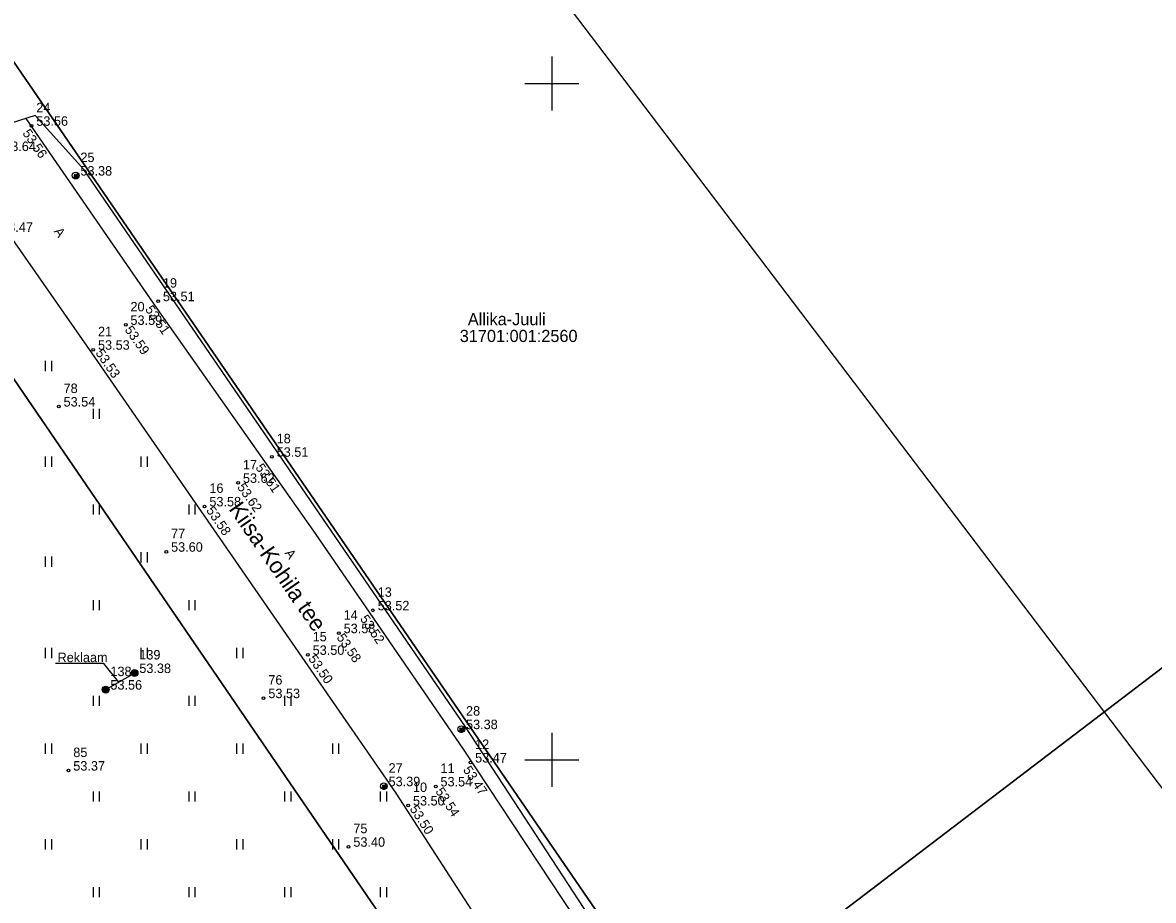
# Model space of a CAD drawing. Extents: x 538599 to 541973, y 6559689 to 6564516.
# Drawn here: x 540610.9 to 540694.4, y 6561289.6 to 6561354.5 of the extents above; entities that cross this region are included whole.
import ezdxf

# ---------------------------------------------------------------- set-up
doc = ezdxf.new("R2010")
doc.units = 0
for name, color, linetype in [('HALJASTUS', 7, 'Continuous'), ('KORGUS-EH2000', 7, 'Continuous'), ('MOOTKORG-EH2000', 7, 'Continuous'), ('MOOTMPUNKT', 7, 'Continuous'), ('MOOTNR', 7, 'Continuous'), ('MOOTPIIR', 7, 'Continuous'), ('PIIR', 7, 'Continuous'), ('POST', 7, 'Continuous'), ('RAJATIS', 7, 'Continuous'), ('TEE', 7, 'Continuous'), ('VORK', 7, 'Continuous'), ('VORMISTUS', 7, 'Continuous')]:
    doc.layers.add(name, color=color, linetype=linetype)

msp = doc.modelspace()

# ---------------------------------------------------------------- linework, layer by layer
at = {"layer": 'HALJASTUS'}
for p, q in [((540612.567, 6561329.498), (540612.567, 6561328.737)), ((540613.022, 6561329.498), (540613.022, 6561328.737)), ((540616.103, 6561325.962), (540616.103, 6561325.201)), ((540616.558, 6561325.962), (540616.558, 6561325.201)), ((540612.567, 6561322.427), (540612.567, 6561321.666)), ((540613.022, 6561322.427), (540613.022, 6561321.666)), ((540619.638, 6561322.427), (540619.638, 6561321.666)), ((540620.093, 6561322.427), (540620.093, 6561321.666)), ((540616.103, 6561318.891), (540616.103, 6561318.13)), ((540616.558, 6561318.891), (540616.558, 6561318.13)), ((540623.174, 6561318.891), (540623.174, 6561318.13)), ((540623.629, 6561318.891), (540623.629, 6561318.13)), ((540612.567, 6561315.033), (540612.567, 6561314.271)), ((540613.022, 6561315.033), (540613.022, 6561314.271)), ((540619.638, 6561315.356), (540619.638, 6561314.595)), ((540620.093, 6561315.356), (540620.093, 6561314.595)), ((540616.103, 6561311.82), (540616.103, 6561311.059)), ((540616.558, 6561311.82), (540616.558, 6561311.059)), ((540623.174, 6561311.82), (540623.174, 6561311.059)), ((540623.629, 6561311.82), (540623.629, 6561311.059)), ((540612.567, 6561308.285), (540612.567, 6561307.524)), ((540613.022, 6561308.285), (540613.022, 6561307.524)), ((540619.638, 6561308.285), (540619.638, 6561307.524)), ((540620.093, 6561308.285), (540620.093, 6561307.524)), ((540626.709, 6561308.285), (540626.709, 6561307.524)), ((540627.164, 6561308.285), (540627.164, 6561307.524)), ((540616.103, 6561304.749), (540616.103, 6561303.988)), ((540616.558, 6561304.749), (540616.558, 6561303.988)), ((540623.174, 6561304.749), (540623.174, 6561303.988)), ((540623.629, 6561304.749), (540623.629, 6561303.988)), ((540630.245, 6561304.749), (540630.245, 6561303.988)), ((540630.7, 6561304.749), (540630.7, 6561303.988)), ((540612.567, 6561301.214), (540612.567, 6561300.453)), ((540613.022, 6561301.214), (540613.022, 6561300.453)), ((540619.638, 6561301.214), (540619.638, 6561300.453)), ((540620.093, 6561301.214), (540620.093, 6561300.453)), ((540626.709, 6561301.214), (540626.709, 6561300.453)), ((540627.164, 6561301.214), (540627.164, 6561300.453)), ((540633.78, 6561301.214), (540633.78, 6561300.453)), ((540634.235, 6561301.214), (540634.235, 6561300.453)), ((540616.103, 6561297.678), (540616.103, 6561296.917)), ((540616.558, 6561297.678), (540616.558, 6561296.917)), ((540623.174, 6561297.678), (540623.174, 6561296.917)), ((540623.629, 6561297.678), (540623.629, 6561296.917)), ((540630.245, 6561297.678), (540630.245, 6561296.917)), ((540630.7, 6561297.678), (540630.7, 6561296.917)), ((540637.316, 6561297.678), (540637.316, 6561296.917)), ((540637.771, 6561297.678), (540637.771, 6561296.917)), ((540612.567, 6561294.143), (540612.567, 6561293.381)), ((540613.022, 6561294.143), (540613.022, 6561293.381)), ((540619.638, 6561294.143), (540619.638, 6561293.381)), ((540620.093, 6561294.143), (540620.093, 6561293.381)), ((540626.709, 6561294.143), (540626.709, 6561293.381)), ((540627.164, 6561294.143), (540627.164, 6561293.381)), ((540633.78, 6561294.143), (540633.78, 6561293.381)), ((540634.235, 6561294.143), (540634.235, 6561293.381)), ((540616.103, 6561290.607), (540616.103, 6561289.846)), ((540616.558, 6561290.607), (540616.558, 6561289.846)), ((540623.174, 6561290.607), (540623.174, 6561289.846)), ((540623.629, 6561290.607), (540623.629, 6561289.846)), ((540630.245, 6561290.607), (540630.245, 6561289.846)), ((540630.7, 6561290.607), (540630.7, 6561289.846)), ((540637.316, 6561290.607), (540637.316, 6561289.846)), ((540637.771, 6561290.607), (540637.771, 6561289.846))]:
    msp.add_line(p, q, dxfattribs=at)
at = {"layer": 'KORGUS-EH2000'}
for centre in [(540611.557, 6561346.872), (540620.91, 6561333.908), (540618.513, 6561332.154), (540616.114, 6561330.319), (540613.571, 6561326.12), (540629.315, 6561322.407), (540626.823, 6561320.477), (540624.343, 6561318.738), (540621.513, 6561315.389), (540636.779, 6561311.056), (540634.264, 6561309.368), (540631.973, 6561307.767), (540628.7, 6561304.567), (540643.977, 6561299.809), (540614.288, 6561299.21), (540641.418, 6561298.042), (540639.384, 6561296.631), (540634.98, 6561293.583)]:
    msp.add_circle(centre, 0.1, dxfattribs=at)
at = {"layer": 'MOOTMPUNKT'}
for centre in [(540611.557, 6561346.872), (540614.816, 6561343.191), (540620.91, 6561333.908), (540618.513, 6561332.154), (540616.114, 6561330.319), (540613.571, 6561326.12), (540629.315, 6561322.407), (540626.823, 6561320.477), (540624.343, 6561318.738), (540621.513, 6561315.389), (540636.779, 6561311.056), (540634.264, 6561309.368), (540631.973, 6561307.767), (540619.167, 6561306.424), (540617.031, 6561305.196), (540628.7, 6561304.567), (540643.306, 6561302.276), (540643.977, 6561299.809), (540614.288, 6561299.21), (540637.582, 6561298.057), (540641.418, 6561298.042), (540639.384, 6561296.631), (540634.98, 6561293.583)]:
    msp.add_circle(centre, 0.1, dxfattribs=at)
at = {"layer": 'MOOTPIIR'}
msp.add_lwpolyline([(540582.869, 6561222.817), (540621.742, 6561247.747), (540640.195, 6561259.582), (540660.245, 6561276.551), (540652.795, 6561288.389), (540643.616, 6561302.458), (540615.416, 6561343.631), (540611.814, 6561347.628), (540600.551, 6561344.045)], dxfattribs=at)
at = {"layer": 'PIIR'}
for points in [[(540290.72, 6561746.68), (540427.24, 6561588.74), (540493.94, 6561511.13), (540543.58, 6561450.93), (540540.24, 6561448.03), (540578.89, 6561396.62), (540600.99, 6561365.08), (540659.54, 6561279.7), (540697.59, 6561212.89), (540728.6, 6561157.63), (540756.94, 6561107.21), (540762.6, 6561098.5), (540765.3, 6561101.59), (540815.83, 6561019.53), (540863.6, 6560935.22), (540880.61, 6560910.09), (540903.4, 6560875.14), (540927.11, 6560842.51), (540955.71, 6560805.99), (540982.2, 6560772.63), (541049.12, 6560693.03)], [(541045.65, 6560666.8), (540964.7, 6560765.19), (540868.94, 6560895.75), (540756.19, 6561084.56), (540744.95, 6561099.98), (540716.4, 6561150.76), (540687.02, 6561204.55), (540646.74, 6561272.89), (540640.63, 6561283.66), (540606.26, 6561333.96), (540569.6, 6561385.93), (540537.11, 6561431.06), (540500.82, 6561475.34), (540460.86, 6561522.64), (540423.13, 6561566.69), (540380.29, 6561616.49), (540342.1, 6561660.8)]]:
    msp.add_lwpolyline(points, dxfattribs=at)
for points in [[(540600.99, 6561365.08), (540701.8, 6561446.25), (540826.84, 6561548.44), (540828.67, 6561550.37), (540829.75, 6561549.48), (540833.57, 6561546.34), (540844.1, 6561537.92), (540853.65, 6561531.83), (540859.93, 6561522.78), (540863.38, 6561506.22), (540873.29, 6561464.28), (540881.92, 6561432.26), (540885.77, 6561408.65), (540892.47, 6561398.48), (540907.42, 6561381.68), (540938.49, 6561347.15), (540935.17, 6561343.58), (540808.31, 6561283.67), (540793.04, 6561301.15), (540771.58, 6561325.47), (540750.46, 6561349.5), (540705.14, 6561314.47), (540659.54, 6561279.7)], [(540535.92, 6561287.97), (540606.26, 6561333.96), (540640.63, 6561283.66), (540573.77, 6561238.75)], [(540659.54, 6561279.7), (540705.14, 6561314.47), (540727.47, 6561291.02), (540772.2, 6561324.85), (540793.34, 6561300.57), (540697.59, 6561212.89)]]:
    msp.add_lwpolyline(points, close=True, dxfattribs=at)
at = {"layer": 'POST'}
for p, q in [((540614.639, 6561343.015), (540614.993, 6561343.368)), ((540643.129, 6561302.1), (540643.483, 6561302.453)), ((540637.405, 6561297.881), (540637.759, 6561298.234))]:
    msp.add_line(p, q, dxfattribs=at)
for centre, radius in [((540614.816, 6561343.191), 0.25), ((540619.167, 6561306.424), 0.25), ((540619.167, 6561306.424), 0.225), ((540619.167, 6561306.424), 0.2), ((540619.167, 6561306.424), 0.175), ((540619.167, 6561306.424), 0.15), ((540619.167, 6561306.424), 0.125), ((540619.167, 6561306.424), 0.1), ((540619.167, 6561306.424), 0.075), ((540619.167, 6561306.424), 0.05), ((540619.167, 6561306.424), 0.025), ((540617.031, 6561305.196), 0.25), ((540617.031, 6561305.196), 0.225), ((540617.031, 6561305.196), 0.2), ((540617.031, 6561305.196), 0.175), ((540617.031, 6561305.196), 0.15), ((540617.031, 6561305.196), 0.125), ((540617.031, 6561305.196), 0.1), ((540617.031, 6561305.196), 0.075), ((540617.031, 6561305.196), 0.05), ((540617.031, 6561305.196), 0.025), ((540643.306, 6561302.276), 0.25), ((540637.582, 6561298.057), 0.25)]:
    msp.add_circle(centre, radius, dxfattribs=at)
for centre, radius, start, end in [((540614.816, 6561343.191), 0.225, 224.85406, 45.03563), ((540614.816, 6561343.191), 0.2, 224.84272, 45.04698), ((540614.816, 6561343.191), 0.175, 224.82813, 45.06157), ((540614.816, 6561343.191), 0.15, 224.80867, 45.08103), ((540614.816, 6561343.191), 0.125, 224.78144, 45.10826), ((540614.816, 6561343.191), 0.1, 224.74058, 45.14911), ((540614.816, 6561343.191), 0.075, 224.67249, 45.2172), ((540614.816, 6561343.191), 0.05, 224.53632, 45.35338), ((540614.816, 6561343.191), 0.025, 224.12776, 45.76193), ((540643.306, 6561302.276), 0.225, 224.85406, 45.03563), ((540643.306, 6561302.276), 0.2, 224.84272, 45.04698), ((540643.306, 6561302.276), 0.175, 224.82813, 45.06157), ((540643.306, 6561302.276), 0.15, 224.80867, 45.08103), ((540643.306, 6561302.276), 0.125, 224.78144, 45.10826), ((540643.306, 6561302.276), 0.1, 224.74058, 45.14911), ((540643.306, 6561302.276), 0.075, 224.67249, 45.2172), ((540643.306, 6561302.276), 0.05, 224.53632, 45.35338), ((540643.306, 6561302.276), 0.025, 224.12776, 45.76193), ((540637.582, 6561298.057), 0.225, 224.85406, 45.03563), ((540637.582, 6561298.057), 0.2, 224.84272, 45.04698), ((540637.582, 6561298.057), 0.175, 224.82813, 45.06157), ((540637.582, 6561298.057), 0.15, 224.80867, 45.08103), ((540637.582, 6561298.057), 0.125, 224.78144, 45.10826), ((540637.582, 6561298.057), 0.1, 224.74058, 45.14911), ((540637.582, 6561298.057), 0.075, 224.67249, 45.2172), ((540637.582, 6561298.057), 0.05, 224.53632, 45.35338), ((540637.582, 6561298.057), 0.025, 224.12776, 45.76193)]:
    msp.add_arc(centre, radius, start, end, dxfattribs=at)
at = {"layer": 'RAJATIS'}
for points in [[(540618.011, 6561305.759), (540616.903, 6561307.116), (540613.318, 6561307.116)], [(540617.031, 6561305.196), (540619.167, 6561306.424)]]:
    msp.add_lwpolyline(points, dxfattribs=at)
at = {"layer": 'TEE'}
for points in [[(540611.142, 6561347.415), (540620.815, 6561333.355), (540632.508, 6561316.728), (540643.438, 6561300.807), (540653.575, 6561285.476), (540659.181, 6561275.65)], [(540654.57, 6561271.748), (540648.314, 6561282.335), (540638.501, 6561297.54), (540627.363, 6561313.661), (540616.232, 6561329.779), (540605.221, 6561345.531)]]:
    msp.add_lwpolyline(points, dxfattribs=at)
at = {"layer": 'VORK'}
for p, q in [((540650, 6561352), (540650, 6561348)), ((540648, 6561350), (540652, 6561350)), ((540650, 6561302), (540650, 6561298)), ((540648, 6561300), (540652, 6561300))]:
    msp.add_line(p, q, dxfattribs=at)
at = {"layer": 'VORMISTUS'}
msp.add_lwpolyline([(540437.607, 6561637.113), (540710.791, 6561277.184), (540482.182, 6561103.671), (540208.998, 6561463.6)], close=True, dxfattribs=at)

# ---------------------------------------------------------------- texts
at = {"layer": 'KORGUS-EH2000'}
for s, rotation, p in [('53.56', 304.52789, (540610.854, 6561346.326)), ('53.51', 305.11695, (540619.915, 6561333.293)), ('53.59', 305.11695, (540618.403, 6561331.789)), ('53.53', 304.62874, (540616.248, 6561330.076)), ('53.51', 305.11695, (540628.068, 6561321.601)), ('53.62', 305.11695, (540626.719, 6561320.154)), ('53.58', 304.62874, (540624.429, 6561318.44)), ('53.52', 304.47017, (540635.792, 6561310.43)), ('53.58', 304.47017, (540634.062, 6561309.047)), ('53.50', 304.6406, (540631.971, 6561307.476)), ('53.47', 303.47305, (540643.401, 6561299.268)), ('53.54', 303.47305, (540641.362, 6561297.677)), ('53.50', 302.83738, (540639.464, 6561296.381))]:
    msp.add_text(s, height=0.7, rotation=rotation, dxfattribs=at).set_placement(p)
for s, p in [('53.54', (540613.921, 6561326.12)), ('53.60', (540621.863, 6561315.389)), ('53.53', (540629.05, 6561304.567)), ('53.37', (540614.638, 6561299.21)), ('53.40', (540635.33, 6561293.583))]:
    msp.add_text(s, height=0.7, dxfattribs=at).set_placement(p)
at = {"layer": 'MOOTKORG-EH2000'}
for s, p in [('53.56', (540611.907, 6561346.872)), ('53.64', (540609.533, 6561345.005)), ('53.38', (540615.166, 6561343.191)), ('53.47', (540609.312, 6561339.032)), ('53.51', (540621.26, 6561333.908)), ('53.59', (540618.863, 6561332.154)), ('53.53', (540616.464, 6561330.319)), ('53.54', (540613.921, 6561326.12)), ('53.51', (540629.665, 6561322.407)), ('53.62', (540627.173, 6561320.477)), ('53.58', (540624.693, 6561318.738)), ('53.60', (540621.863, 6561315.389)), ('53.52', (540637.129, 6561311.056)), ('53.58', (540634.614, 6561309.368)), ('53.50', (540632.323, 6561307.767)), ('53.38', (540619.517, 6561306.424)), ('53.56', (540617.381, 6561305.196)), ('53.53', (540629.05, 6561304.567)), ('53.38', (540643.656, 6561302.276)), ('53.37', (540614.638, 6561299.21)), ('53.47', (540644.327, 6561299.809)), ('53.39', (540637.932, 6561298.057)), ('53.54', (540641.768, 6561298.042)), ('53.50', (540639.734, 6561296.631)), ('53.40', (540635.33, 6561293.583))]:
    msp.add_text(s, height=0.7, dxfattribs=at).set_placement(p)
at = {"layer": 'MOOTNR'}
for s, p in [('24', (540611.907, 6561347.872)), ('25', (540615.166, 6561344.191)), ('19', (540621.26, 6561334.908)), ('20', (540618.863, 6561333.154)), ('21', (540616.464, 6561331.319)), ('78', (540613.921, 6561327.12)), ('18', (540629.665, 6561323.407)), ('17', (540627.173, 6561321.477)), ('16', (540624.693, 6561319.738)), ('77', (540621.863, 6561316.389)), ('13', (540637.129, 6561312.056)), ('14', (540634.614, 6561310.368)), ('15', (540632.323, 6561308.767)), ('139', (540619.517, 6561307.424)), ('138', (540617.381, 6561306.196)), ('76', (540629.05, 6561305.567)), ('28', (540643.656, 6561303.276)), ('12', (540644.327, 6561300.809)), ('85', (540614.638, 6561300.21)), ('27', (540637.932, 6561299.057)), ('11', (540641.768, 6561299.042)), ('10', (540639.734, 6561297.631)), ('75', (540635.33, 6561294.583))]:
    msp.add_text(s, height=0.7, dxfattribs=at).set_placement(p)
at = {"layer": 'PIIR'}
for s, p in [('Allika-Juuli', (540643.788, 6561332.131)), ('31701:001:2560', (540643.191, 6561330.889))]:
    msp.add_text(s, height=0.9, rotation=0, dxfattribs=at).set_placement(p)
at = {"layer": 'RAJATIS'}
msp.add_text('Reklaam', height=0.7, dxfattribs=at).set_placement((540613.479, 6561307.228))
at = {"layer": 'TEE'}
for s, height, rotation, p in [('A', 0.7, 304.95353, (540613.179, 6561339.062)), ('Kiisa-Kohila tee', 1.2, 304.6406, (540626.085, 6561318.545)), ('A', 0.7, 304.6406, (540630.232, 6561315.285))]:
    msp.add_text(s, height=height, rotation=rotation, dxfattribs=at).set_placement(p)

doc.saveas('drawing.dxf')
